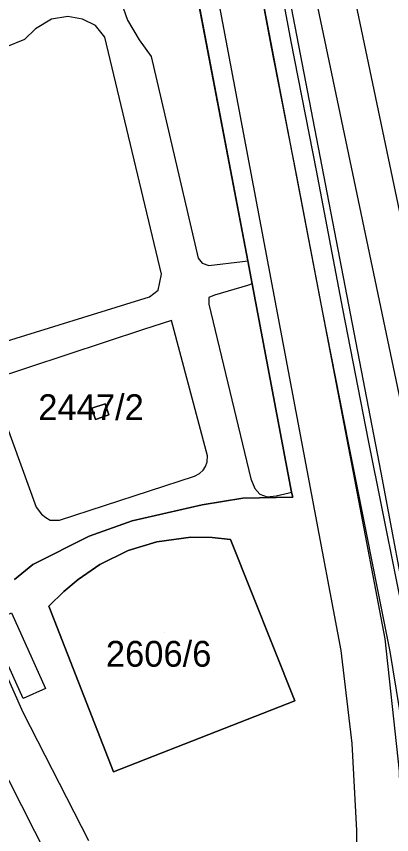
# Model space of a CAD drawing. Extents: x -263423 to -261326, y -1240067 to -1237864.
# Drawn here: x -262739.6 to -262710.5, y -1239766.9 to -1239703.5 of the extents above; entities that cross this region are included whole.
import ezdxf

# ---------------------------------------------------------------- set-up
doc = ezdxf.new("R2010")
doc.units = 0
for name, color, linetype in [('body_kn', 7, 'Continuous'), ('kladpar_druhypozemkov', 7, 'Continuous'), ('kladpar_hranice', 7, 'Continuous'), ('kladpar_parcelnecisla', 7, 'Continuous'), ('kladpar_plochy', 7, 'Continuous'), ('tarchy_linie', 7, 'Continuous'), ('zappar_hrandruhpozemk', 7, 'Continuous')]:
    doc.layers.add(name, color=color, linetype=linetype)

msp = doc.modelspace()

# ---------------------------------------------------------------- linework, layer by layer
at = {"layer": 'body_kn'}
for p, q in [((-262735.63, -1239703.49), (-262735.63, -1239703.49)), ((-262736.9, -1239703.7), (-262736.9, -1239703.7)), ((-262736.9, -1239703.7), (-262736.9, -1239703.7)), ((-262734.49, -1239703.69), (-262734.49, -1239703.69)), ((-262733.5, -1239704.18), (-262733.5, -1239704.18)), ((-262731.01, -1239703.78), (-262731.01, -1239703.78)), ((-262738.13, -1239704.44), (-262738.13, -1239704.44)), ((-262739, -1239705.28), (-262739, -1239705.28)), ((-262732.78, -1239705.1), (-262732.78, -1239705.1)), ((-262730.12, -1239705.31), (-262730.12, -1239705.31)), ((-262718.35, -1239705.44), (-262718.35, -1239705.44)), ((-262719.9, -1239705.74), (-262719.9, -1239705.74)), ((-262729.17, -1239706.59), (-262729.17, -1239706.59)), ((-262716.4, -1239715.43), (-262716.4, -1239715.43)), ((-262717.95, -1239715.73), (-262717.95, -1239715.73)), ((-262725.53, -1239722.21), (-262725.53, -1239722.21)), ((-262725.22, -1239722.6), (-262725.22, -1239722.6)), ((-262722.1, -1239722.48), (-262722.1, -1239722.48)), ((-262721.69, -1239722.43), (-262721.69, -1239722.43)), ((-262724.71, -1239722.79), (-262724.71, -1239722.79)), ((-262728.37, -1239723.47), (-262728.37, -1239723.47)), ((-262721.72, -1239724.33), (-262721.72, -1239724.33)), ((-262721.35, -1239724.22), (-262721.35, -1239724.22)), ((-262721.35, -1239724.22), (-262721.35, -1239724.22)), ((-262728.63, -1239724.7), (-262728.63, -1239724.7)), ((-262724.27, -1239725.09), (-262724.27, -1239725.09)), ((-262729.31, -1239725.22), (-262729.31, -1239725.22)), ((-262724.72, -1239725.28), (-262724.72, -1239725.28)), ((-262724.72, -1239725.78), (-262724.72, -1239725.78)), ((-262715.91, -1239726.44), (-262715.91, -1239726.44)), ((-262714.36, -1239726.14), (-262714.36, -1239726.14)), ((-262727.61, -1239727.04), (-262727.61, -1239727.04)), ((-262727.61, -1239727.04), (-262727.61, -1239727.04)), ((-262729.76, -1239727.74), (-262729.76, -1239727.74)), ((-262733.77, -1239733.84), (-262733.77, -1239733.84)), ((-262733.77, -1239733.84), (-262733.77, -1239733.84)), ((-262732.74, -1239733.5), (-262732.74, -1239733.5)), ((-262732.45, -1239734.37), (-262732.45, -1239734.37)), ((-262733.49, -1239734.73), (-262733.49, -1239734.73)), ((-262712.35, -1239736.36), (-262712.35, -1239736.36)), ((-262713.89, -1239736.67), (-262713.89, -1239736.67)), ((-262724.81, -1239737.54), (-262724.81, -1239737.54)), ((-262724.96, -1239738.37), (-262724.96, -1239738.37)), ((-262724.83, -1239738), (-262724.83, -1239738)), ((-262725.81, -1239739.11), (-262725.81, -1239739.11)), ((-262725.42, -1239738.91), (-262725.42, -1239738.91)), ((-262725.15, -1239738.66), (-262725.15, -1239738.66)), ((-262711.38, -1239738.84), (-262711.38, -1239738.84)), ((-262721.46, -1239739.31), (-262721.46, -1239739.31)), ((-262713.41, -1239739.36), (-262713.41, -1239739.36)), ((-262721.15, -1239740.07), (-262721.15, -1239740.07)), ((-262718.47, -1239740.4), (-262718.47, -1239740.4)), ((-262718.29, -1239740.35), (-262718.29, -1239740.35)), ((-262722.08, -1239740.82), (-262722.08, -1239740.82)), ((-262720.76, -1239740.52), (-262720.76, -1239740.52)), ((-262720.19, -1239740.71), (-262720.19, -1239740.71)), ((-262719.49, -1239740.65), (-262719.49, -1239740.65)), ((-262718.21, -1239740.75), (-262718.21, -1239740.75)), ((-262716.75, -1239740.43), (-262716.75, -1239740.43)), ((-262738.1, -1239741.52), (-262738.1, -1239741.52)), ((-262725.23, -1239741.33), (-262725.23, -1239741.33)), ((-262737.67, -1239742.06), (-262737.67, -1239742.06)), ((-262737.33, -1239742.33), (-262737.33, -1239742.33)), ((-262737.01, -1239742.52), (-262737.01, -1239742.52)), ((-262736.28, -1239742.53), (-262736.28, -1239742.53)), ((-262730.64, -1239742.58), (-262730.64, -1239742.58)), ((-262733.98, -1239743.76), (-262733.98, -1239743.76)), ((-262728.75, -1239744.2), (-262728.75, -1239744.2)), ((-262726.11, -1239743.85), (-262726.11, -1239743.85)), ((-262724.45, -1239743.86), (-262724.45, -1239743.86)), ((-262723.03, -1239744.02), (-262723.03, -1239744.02)), ((-262723.03, -1239744.02), (-262723.03, -1239744.02)), ((-262730.97, -1239744.88), (-262730.97, -1239744.88)), ((-262738.34, -1239745.97), (-262738.34, -1239745.97)), ((-262733.15, -1239745.97), (-262733.15, -1239745.97)), ((-262734.84, -1239747.12), (-262734.84, -1239747.12)), ((-262735.95, -1239748.05), (-262735.95, -1239748.05)), ((-262737.1, -1239749.19), (-262737.1, -1239749.19)), ((-262711.07, -1239751.72), (-262711.07, -1239751.72)), ((-262714.44, -1239752.62), (-262714.44, -1239752.62)), ((-262710.68, -1239752.7), (-262710.68, -1239752.7)), ((-262737.36, -1239755.57), (-262737.36, -1239755.57)), ((-262739.11, -1239756.35), (-262739.11, -1239756.35)), ((-262718.04, -1239756.53), (-262718.04, -1239756.53)), ((-262739.09, -1239757.43), (-262739.09, -1239757.43)), ((-262713.59, -1239759.83), (-262713.59, -1239759.83)), ((-262732.1, -1239762.02), (-262732.1, -1239762.02)), ((-262713.25, -1239766.57), (-262713.25, -1239766.57))]:
    msp.add_line(p, q, dxfattribs=at)
at = {"layer": 'kladpar_druhypozemkov'}
for p, q in [((-262733.08, -1239734.34), (-262733.08, -1239734.34)), ((-262728.14, -1239751.2), (-262728.14, -1239751.2))]:
    msp.add_line(p, q, dxfattribs=at)
at = {"layer": 'kladpar_hranice'}
for points in [[(-262740.91, -1239625.89), (-262730.13, -1239678.22), (-262729.72, -1239680.22), (-262721.69, -1239722.43), (-262721.35, -1239724.22), (-262718.29, -1239740.35), (-262718.21, -1239740.75), (-262722.08, -1239740.82), (-262725.23, -1239741.33), (-262730.64, -1239742.58), (-262733.98, -1239743.76), (-262738.34, -1239745.97), (-262739.76, -1239747.13)], [(-262739.76, -1239747.13), (-262738.34, -1239745.97), (-262733.98, -1239743.76), (-262730.64, -1239742.58), (-262725.23, -1239741.33), (-262722.08, -1239740.82), (-262718.21, -1239740.75), (-262718.29, -1239740.35), (-262721.35, -1239724.22), (-262721.69, -1239722.43), (-262729.72, -1239680.22), (-262730.13, -1239678.22), (-262740.91, -1239625.89)], [(-262733.77, -1239733.84), (-262732.74, -1239733.5), (-262732.45, -1239734.37), (-262733.49, -1239734.73), (-262733.77, -1239733.84)], [(-262732.74, -1239733.5), (-262733.77, -1239733.84), (-262733.49, -1239734.73), (-262732.45, -1239734.37), (-262732.74, -1239733.5)], [(-262723.03, -1239744.02), (-262718.04, -1239756.53), (-262732.1, -1239762.02), (-262737.1, -1239749.19), (-262735.95, -1239748.05), (-262734.84, -1239747.12), (-262733.15, -1239745.97), (-262730.97, -1239744.88), (-262728.75, -1239744.2), (-262726.11, -1239743.85), (-262724.45, -1239743.86), (-262723.03, -1239744.02)], [(-262718.04, -1239756.53), (-262723.03, -1239744.02), (-262724.45, -1239743.86), (-262726.11, -1239743.85), (-262728.75, -1239744.2), (-262730.97, -1239744.88), (-262733.15, -1239745.97), (-262734.84, -1239747.12), (-262735.95, -1239748.05), (-262737.1, -1239749.19), (-262732.1, -1239762.02), (-262718.04, -1239756.53)]]:
    msp.add_lwpolyline(points, dxfattribs=at)
at = {"layer": 'kladpar_plochy'}
for p, q in [((-262729.72, -1239680.22), (-262721.69, -1239722.43)), ((-262721.69, -1239722.43), (-262729.72, -1239680.22)), ((-262721.69, -1239722.43), (-262721.35, -1239724.22)), ((-262721.35, -1239724.22), (-262721.69, -1239722.43)), ((-262721.35, -1239724.22), (-262718.29, -1239740.35)), ((-262718.29, -1239740.35), (-262721.35, -1239724.22)), ((-262732.74, -1239733.5), (-262733.77, -1239733.84)), ((-262733.77, -1239733.84), (-262733.49, -1239734.73)), ((-262732.45, -1239734.37), (-262732.74, -1239733.5)), ((-262733.49, -1239734.73), (-262732.45, -1239734.37)), ((-262718.29, -1239740.35), (-262718.21, -1239740.75)), ((-262718.21, -1239740.75), (-262718.29, -1239740.35)), ((-262722.08, -1239740.82), (-262725.23, -1239741.33)), ((-262725.23, -1239741.33), (-262722.08, -1239740.82)), ((-262718.21, -1239740.75), (-262722.08, -1239740.82)), ((-262722.08, -1239740.82), (-262718.21, -1239740.75)), ((-262725.23, -1239741.33), (-262730.64, -1239742.58)), ((-262730.64, -1239742.58), (-262725.23, -1239741.33)), ((-262730.64, -1239742.58), (-262733.98, -1239743.76)), ((-262733.98, -1239743.76), (-262730.64, -1239742.58)), ((-262733.98, -1239743.76), (-262738.34, -1239745.97)), ((-262738.34, -1239745.97), (-262733.98, -1239743.76)), ((-262728.75, -1239744.2), (-262730.97, -1239744.88)), ((-262726.11, -1239743.85), (-262728.75, -1239744.2)), ((-262724.45, -1239743.86), (-262726.11, -1239743.85)), ((-262723.03, -1239744.02), (-262724.45, -1239743.86)), ((-262718.04, -1239756.53), (-262723.03, -1239744.02)), ((-262730.97, -1239744.88), (-262733.15, -1239745.97)), ((-262738.34, -1239745.97), (-262739.76, -1239747.13)), ((-262739.76, -1239747.13), (-262738.34, -1239745.97)), ((-262733.15, -1239745.97), (-262734.84, -1239747.12)), ((-262734.84, -1239747.12), (-262735.95, -1239748.05)), ((-262735.95, -1239748.05), (-262737.1, -1239749.19)), ((-262737.1, -1239749.19), (-262732.1, -1239762.02)), ((-262732.1, -1239762.02), (-262718.04, -1239756.53))]:
    msp.add_line(p, q, dxfattribs=at)
for points in [[(-262733.77, -1239733.84), (-262732.74, -1239733.5), (-262732.45, -1239734.37), (-262733.49, -1239734.73)], [(-262723.03, -1239744.02), (-262718.04, -1239756.53), (-262732.1, -1239762.02), (-262737.1, -1239749.19), (-262735.95, -1239748.05), (-262734.84, -1239747.12), (-262733.15, -1239745.97), (-262730.97, -1239744.88), (-262728.75, -1239744.2), (-262726.11, -1239743.85), (-262724.45, -1239743.86)]]:
    msp.add_lwpolyline(points, close=True, dxfattribs=at)
at = {"layer": 'tarchy_linie'}
for points in [[(-262876.1, -1239267.26), (-262859.65, -1239272.11), (-262836.46, -1239332.83), (-262813.8, -1239395.79), (-262782.96, -1239480.21), (-262751.68, -1239564.86), (-262738.56, -1239596.25), (-262720.83, -1239681.08), (-262703.16, -1239765.24), (-262676.39, -1239868.22), (-262673.88, -1239876.15)], [(-262748.93, -1239563.78), (-262735.73, -1239595.37), (-262717.94, -1239680.48), (-262700.29, -1239764.57), (-262673.55, -1239867.4)], [(-262739.93, -1239594.25), (-262736.99, -1239604.52), (-262734.56, -1239614.45), (-262732.52, -1239624.43), (-262730.56, -1239634.88), (-262728.68, -1239644.46), (-262726.88, -1239654.48), (-262725.41, -1239664.84), (-262724.09, -1239674.85), (-262722.07, -1239685.48), (-262720.17, -1239695.75), (-262718.35, -1239705.44), (-262716.4, -1239715.43), (-262714.36, -1239726.14), (-262712.35, -1239736.36), (-262709.13, -1239752.42), (-262707.17, -1239764.28), (-262706.65, -1239767.73), (-262706.19, -1239774), (-262705.77, -1239786.06), (-262699.88, -1239808.04), (-262689.6, -1239849.41)], [(-262741.39, -1239597.13), (-262726.59, -1239667.94), (-262725.65, -1239675.1), (-262723.62, -1239685.77), (-262721.72, -1239696.04), (-262719.9, -1239705.74), (-262717.95, -1239715.73), (-262715.91, -1239726.44), (-262713.89, -1239736.67), (-262710.68, -1239752.7), (-262708.73, -1239764.53), (-262708.22, -1239767.91), (-262707.76, -1239774.09), (-262707.34, -1239786.29), (-262701.41, -1239808.43), (-262691.04, -1239850.16)], [(-262741.75, -1239750.49), (-262740, -1239749.71), (-262737.36, -1239755.57), (-262739.11, -1239756.35), (-262741.75, -1239750.49)]]:
    msp.add_lwpolyline(points, dxfattribs=at)
at = {"layer": 'zappar_hrandruhpozemk'}
for p, q in [((-262728.37, -1239723.47), (-262732.78, -1239705.1)), ((-262724.72, -1239725.78), (-262721.46, -1239739.31)), ((-262739.09, -1239757.43), (-262749.57, -1239734)), ((-262736.28, -1239742.53), (-262725.81, -1239739.11)), ((-262713.59, -1239759.83), (-262714.44, -1239752.62)), ((-262734.02, -1239767.37), (-262739.09, -1239757.43))]:
    msp.add_line(p, q, dxfattribs=at)
for points in [[(-262724.9, -1239679.49), (-262713.41, -1239739.36), (-262711.07, -1239751.72), (-262709.96, -1239761.98), (-262709.78, -1239769.09)], [(-262722.9, -1239679.06), (-262711.38, -1239738.84), (-262709.03, -1239751.34)], [(-262714.44, -1239752.62), (-262716.75, -1239740.43), (-262728.13, -1239680.12)], [(-262731.51, -1239702.37), (-262731.01, -1239703.78), (-262730.12, -1239705.31), (-262729.17, -1239706.59), (-262725.53, -1239722.21), (-262725.22, -1239722.6), (-262724.71, -1239722.79), (-262722.1, -1239722.48), (-262721.69, -1239722.43)], [(-262732.78, -1239705.1), (-262733.5, -1239704.18), (-262734.49, -1239703.69), (-262735.63, -1239703.49), (-262736.9, -1239703.7)], [(-262736.9, -1239703.7), (-262738.13, -1239704.44), (-262739, -1239705.28), (-262740.52, -1239705.9), (-262742.42, -1239706.34), (-262745.57, -1239706.76), (-262747.44, -1239707.06), (-262748.56, -1239707.46), (-262749.53, -1239708.09), (-262750.08, -1239709.48), (-262750.06, -1239710.89), (-262749.23, -1239714.86), (-262748.09, -1239718.48)], [(-262745.27, -1239724.56), (-262742.91, -1239728.47), (-262742.42, -1239728.9), (-262741.5, -1239729), (-262729.31, -1239725.22), (-262728.63, -1239724.7), (-262728.37, -1239723.47)], [(-262721.35, -1239724.22), (-262721.72, -1239724.33), (-262724.27, -1239725.09), (-262724.72, -1239725.28), (-262724.72, -1239725.78)], [(-262727.61, -1239727.04), (-262729.76, -1239727.74), (-262741.67, -1239731.67), (-262738.1, -1239741.52), (-262737.67, -1239742.06), (-262737.33, -1239742.33), (-262737.01, -1239742.52), (-262736.28, -1239742.53)], [(-262725.81, -1239739.11), (-262725.42, -1239738.91), (-262725.15, -1239738.66), (-262724.96, -1239738.37), (-262724.83, -1239738), (-262724.81, -1239737.54), (-262727.61, -1239727.04)], [(-262752.45, -1239735.52), (-262742.22, -1239758.77), (-262737.25, -1239768.56), (-262731.89, -1239777.14)], [(-262721.46, -1239739.31), (-262721.15, -1239740.07), (-262720.76, -1239740.52), (-262720.19, -1239740.71), (-262719.49, -1239740.65), (-262718.47, -1239740.4), (-262718.29, -1239740.35)], [(-262713.36, -1239784.74), (-262713.22, -1239776.52), (-262713.25, -1239766.57), (-262713.59, -1239759.83)]]:
    msp.add_lwpolyline(points, dxfattribs=at)

# ---------------------------------------------------------------- texts
at = {"layer": 'kladpar_parcelnecisla'}
for s, p in [('2447/2', (-262737.926, -1239734.77)), ('2606/6', (-262732.688, -1239753.88))]:
    msp.add_text(s, height=2, dxfattribs=at).set_placement(p)

doc.saveas('drawing.dxf')
